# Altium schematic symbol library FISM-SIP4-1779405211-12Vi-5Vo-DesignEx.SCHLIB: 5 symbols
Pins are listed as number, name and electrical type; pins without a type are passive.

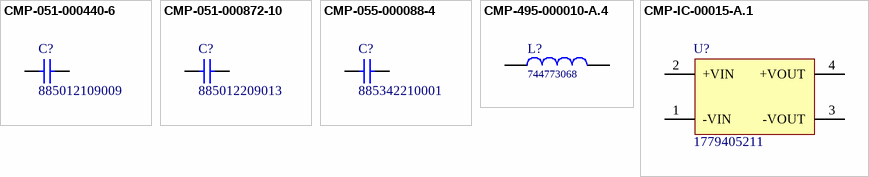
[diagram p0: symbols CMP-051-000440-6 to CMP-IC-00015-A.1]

## CMP-051-000440-6
designator C?, comment 885012109009
WCAP-CSGP Multilayer Ceramic Chip Capacitor, General Purpose, size 1210, X5R, 10uF, 16V; Manufacturer: Wurth Electronics; Rated Voltage: 16VDC; Isolation Resistance: >=0.05GOhm; Capacitance Tolerance: +/-20%; Technical Reference: X5R1210106M016DFCT10000; Provided by WE: Yes
footprint WCAP-CSGP_1210_H=2mm (Ceramic Capacitors, body 3.2x2.5mm)
pins: 1, 1, 2, 2

## CMP-051-000872-10
designator C?, comment 885012209013
WCAP-CSGP Multilayer Ceramic Chip Capacitor, General Purpose, size 1210, X7R, 4.7uF, 16V; Manufacturer: Wurth Electronics; Capacitance Tolerance: +/-10%; Isolation Resistance: >=0.1GOhm; Technical Reference: X7R1210475K016DFCT10000; Rated Voltage: 16VDC
footprint WCAP-CSGP_1210_H=2mm (Ceramic Capacitors, body 3.2x2.5mm)
pins: 1, 2

## CMP-055-000088-4
designator C?, comment 885342210001
WCAP-CSMH Multilayer Ceramic Chip Capacitor, size 1808, X7R Class II, 1nF, 2000V; Manufacturer: Wurth Electronics; Dissipation Factor: 2.5%; Technical Reference: X7R1808102KB00DFCT10000; Provided by WE: Yes; Capacitance Tolerance: +/-10%; Insulation Resistance: 10GOhm; Rated Voltage: 2000VDC
footprint WCAP-CSMH_1808_H1.25 (Ceramic Capacitors, body 4.5x2.03mm)
pins: 1, 2

## CMP-495-000010-A.4
designator L?, comment 744773068
WE-PD2 SMT Power Inductor, size 4532, 6.8uH, 1.54A; Manufacturer: Wurth Electronics; DC Resistance typ.: 0.076Ohm; Self Resonant Frequency: 41MHz; Saturation Current: 2.1A; DC Resistance max.: 0.131Ohm
footprint WE-PD2_4532 (SMD Power Inductor, 2-Leads, body 4x4.5mm)
pins: 1, 2

## CMP-IC-00015-A.1
designator U?, comment 1779405211
WPME-FISM Fixed Isolated Module, SIP-4, 10.8-13.2Vin, 5Vout; Manufacturer: Wurth Elektronik; Output Voltage: 5V; Input Voltage: 12V; Isolation Voltage: 1.5kV; Input Voltage Max: 13.2V; Input Voltage Min: 10.8V
footprint WPME-FISM_SIP-4_L11.6W7.55H10.16 (Power Module, SIP-4, body 11.60x7.55mm)
pins: 1 -VIN, 2 +VIN, 3 -VOUT, 4 +VOUT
